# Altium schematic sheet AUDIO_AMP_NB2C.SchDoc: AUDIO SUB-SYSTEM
size A4; Organization: Altium Limited.; Address1: 3 Minna Close; Address2: Belrose; Address3: NSW 2085; Address4: AUSTRALIA; DocumentNumber: 16; SheetNumber: 17; SheetTotal: 78; PageSetup: Record=PageOptions|CenterHorizontal=True|CenterVertical=True|PrintScale=0.97|XCorrection=1.00|YCorrection=1.00|PrintKind=0|BorderSize=5000000|LeftOffset=0|BottomOffset=0|Orientation=2|PaperLength=1000|PaperWidth=1000|Scale=100|PaperSource=7|PrintQuality=-4|MediaType=1|DitherType=10|PaperKind=A4 (210 x 297 mm)|PrintScaleMode=1
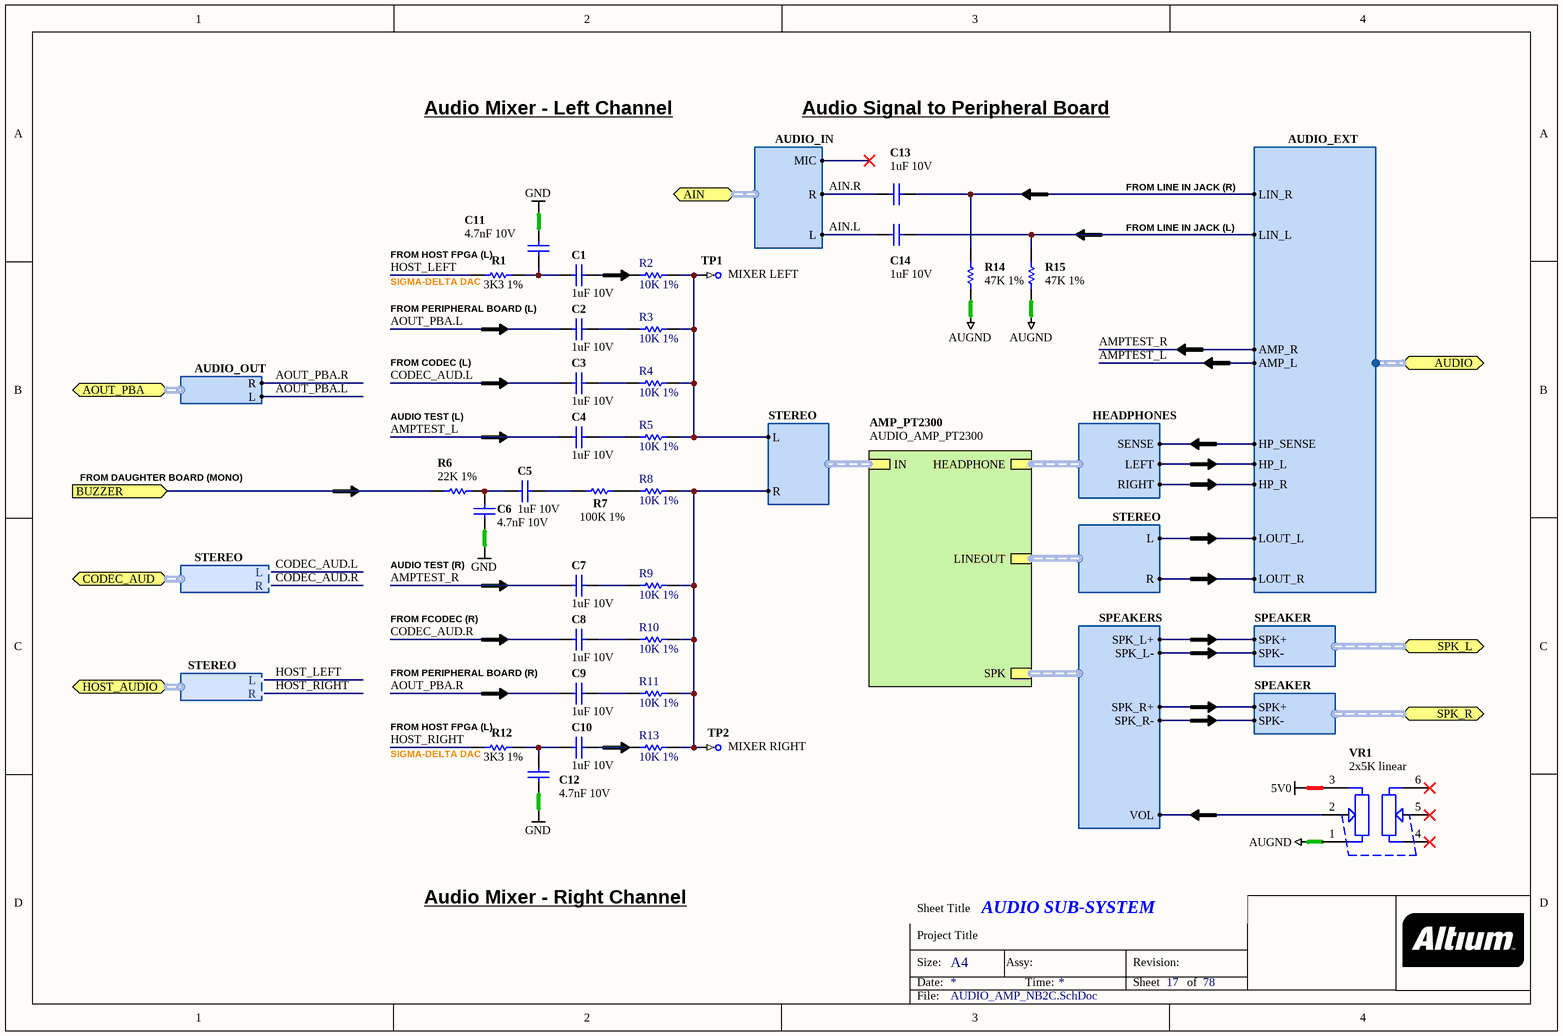
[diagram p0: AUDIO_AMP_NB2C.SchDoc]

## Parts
C1  1uF 10V  [CAPC1005-STAR]
C2  1uF 10V  [CAPC1005-STAR]
C3  1uF 10V  [CAPC1005-STAR]
C4  1uF 10V  [CAPC1005-STAR]
C5  1uF 10V  [CAPC1005-STAR]
C6  4.7nF 10V  [CAPC1005-STAR]
C7  1uF 10V  [CAPC1005-STAR]
C8  1uF 10V  [CAPC1005-STAR]
C9  1uF 10V  [CAPC1005-STAR]
C10  1uF 10V  [CAPC1005-STAR]
C11  4.7nF 10V  [CAPC1005-STAR]
C12  4.7nF 10V  [CAPC1005-STAR]
C13  1uF 10V  [CAPC1005-STAR]
C14  1uF 10V  [CAPC1005-STAR]
R1  3K3 1%  [RESC1005-STAR]
R2  10K 1%  [RESC1005-STAR]
R3  10K 1%  [RESC1005-STAR]
R4  10K 1%  [RESC1005-STAR]
R5  10K 1%  [RESC1005-STAR]
R6  22K 1%  [RESC1005-STAR]
R7  100K 1%  [RESC1005-STAR]
R8  10K 1%  [RESC1005-STAR]
R9  10K 1%  [RESC1005-STAR]
R10  10K 1%  [RESC1005-STAR]
R11  10K 1%  [RESC1005-STAR]
R12  3K3 1%  [RESC1005-STAR]
R13  10K 1%  [RESC1005-STAR]
R14  47K 1%  [RESC1005-STAR]
R15  47K 1%  [RESC1005-STAR]
TP1  MIXER LEFT  [TestPin]  (no BOM)
TP2  MIXER RIGHT  [TestPin]  (no BOM)
VR1  2x5K linear  [POT-R0911G-A1]

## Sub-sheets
AMP_PT2300 = AUDIO_AMP_PT2300: SPK (harness SPEAKERS), IN (harness STEREO), LINEOUT (harness STEREO), HEADPHONE (harness HEADPHONES)

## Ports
AIN (harness AUDIO_IN), AOUT_PBA (harness AUDIO_OUT), AUDIO (harness AUDIO_EXT), BUZZER (in), CODEC_AUD (harness STEREO), HOST_AUDIO (harness STEREO), SPK_L (harness SPEAKER), SPK_R (harness SPEAKER)

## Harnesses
AUDIO_EXT: AMP_L, AMP_R, HP_L, HP_R, HP_SENSE, LIN_L, LIN_R, LOUT_L, LOUT_R
STEREO: R, L
HEADPHONES: RIGHT, LEFT, SENSE
SPEAKER: SPK-, SPK+
SPEAKERS: SPK_L-, SPK_L+, SPK_R-, SPK_R+, VOL
AUDIO_IN: L, R, MIC
STEREO: L, R
AUDIO_OUT: L, R

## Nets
5V0: VR1.3
AUGND: R14.1 R15.1 VR1.1
GND: C6.2 C11.2 C12.2
AIN.L: C14.2 ; port AIN.L
AIN.R: C13.2 ; port AIN.R
AMPTEST_L: C4.2 ; port AUDIO.AMP_L
AMPTEST_R: C7.2 ; port AUDIO.AMP_R
AOUT_PBA.L: C2.2 ; port AOUT_PBA.L
AOUT_PBA.R: C9.2 ; port AOUT_PBA.R
BUZZER: R6.1 ; port BUZZER
CODEC_AUD.L: C3.2 ; port CODEC_AUD.L
CODEC_AUD.R: C8.2 ; port CODEC_AUD.R
HOST_LEFT: R1.1 ; port HOST_AUDIO.L
HOST_RIGHT: R12.1 ; port HOST_AUDIO.R
NetC1_1: C1.1 R2.1
NetC1_2: C1.2 C11.1 R1.2
NetC2_1: C2.1 R3.1
NetC3_1: C3.1 R4.1
NetC4_1: C4.1 R5.1
NetC5_1: C5.1 R7.1
NetC5_2: C5.2 C6.1 R6.2
NetC7_1: C7.1 R9.1
NetC8_1: C8.1 R10.1
NetC9_1: C9.1 R11.1
NetC10_1: C10.1 R13.1
NetC10_2: C10.2 C12.1 R12.2
NetC13_1: C13.1 R14.2 ; port AUDIO.LIN_R
NetC14_1: C14.1 R15.2 ; port AUDIO.LIN_L
NetR2_2: R2.2 R3.2 R4.2 R5.2 TP1.1 ; sheet AMP_PT2300/IN.L
NetR7_2: R7.2 R8.1
NetR8_2: R8.2 R9.2 R10.2 R11.2 R13.2 TP2.1 ; sheet AMP_PT2300/IN.R
NetVR1_2: VR1.2 ; sheet AMP_PT2300/SPK.VOL
(unnamed): port AUDIO.HP_L, sheet AMP_PT2300/HEADPHONE.LEFT
(unnamed): port AUDIO.HP_R, sheet AMP_PT2300/HEADPHONE.RIGHT  [a separate net that carries the same name]
(unnamed): port AUDIO.HP_SENSE, sheet AMP_PT2300/HEADPHONE.SENSE  [a separate net that carries the same name]
(unnamed): port AUDIO.LOUT_L, sheet AMP_PT2300/LINEOUT.L  [a separate net that carries the same name]
(unnamed): port AUDIO.LOUT_R, sheet AMP_PT2300/LINEOUT.R  [a separate net that carries the same name]
(unnamed): port SPK_L.SPK-, sheet AMP_PT2300/SPK.SPK_L-  [a separate net that carries the same name]
(unnamed): port SPK_L.SPK+, sheet AMP_PT2300/SPK.SPK_L+  [a separate net that carries the same name]
(unnamed): sheet AMP_PT2300/SPK.SPK_R-, port SPK_R.SPK-  [a separate net that carries the same name]
(unnamed): sheet AMP_PT2300/SPK.SPK_R+, port SPK_R.SPK+  [a separate net that carries the same name]

Not connected (* = marked no-connect by the designer): VR1 4* 5* 6*

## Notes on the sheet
- Audio Mixer - Left Channel
- Audio Signal to Peripheral Board
- FROM LINE IN JACK (R)
- FROM LINE IN JACK (L)
- (near R1) FROM PERIPHERAL BOARD (L)
- (near R1) FROM HOST FPGA (L)
- (near R1) SIGMA-DELTA DAC
- FROM CODEC (L)
- AUDIO TEST (L)
- FROM DAUGHTER BOARD (MONO)
- AUDIO TEST (R)
- FROM FCODEC (R)
- FROM PERIPHERAL BOARD (R)
- (near R12) FROM HOST FPGA (L)
- (near R12) SIGMA-DELTA DAC
- Audio Mixer - Right Channel

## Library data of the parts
C1-C5 C7-C10 C13 C14 = D-101-0131: Capacitor, Ceramic, 1uF 10% 10V 0402 (1005) X5R; Polarity: Non-Polarized
C6 C11 C12 = D-101-0132: Capacitor, Ceramic, 4.7nF 10% 10V 0402 (1005) X7R; Polarity: Non-Polarized
R1 R12 = D-100-0098: Resistor, 3K3 1% 0402 (1005); Power Rating: 63 mW; Resistance: 3.3 K
R2-R5 R8-R11 R13 = D-100-0130: Resistor, 10K 1% 0402 (1005); Power Rating: 63mW
R6 = D-100-0114: Resistor, 22K 1% 0402 (1005); Power Rating: mW
R7 = D-100-0132: Resistor, 100K 1% 0402 (1005); Power Rating: 63 mW
R14 R15 = D-100-0092: Resistor, 47K 1% 0402 (1005); Power Rating: 63 mW
TP1 TP2 = D-006-0000: Test Point, PCB Mount with Silkscreen Box
VR1 = D-105-0001: Potentiometer, 2 x 5K Linear 9mm PCB Mount Fluted Shaft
